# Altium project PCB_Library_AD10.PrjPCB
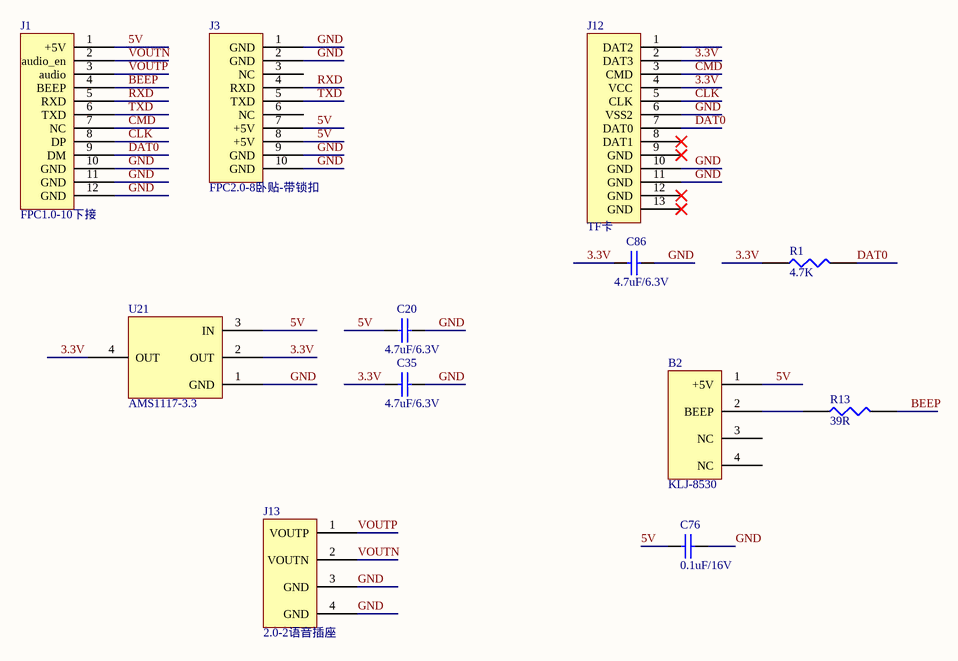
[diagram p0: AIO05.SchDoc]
6 sheets, 75 parts. Net scope: global (net labels, ports and power ports of the same name join across sheets).
Board files: AIO05.PcbDoc, AIO028-A.PcbDoc, AIO028-B.PcbDoc, AIO035-A.PcbDoc, AIO035-B.PcbDoc
Sheets:
  AIO05.SchDoc
  AIO03.SchDoc
  AIO028-A.SchDoc
  AIO028-B.SchDoc
  AIO035-A.SchDoc
  AIO035-B.SchDoc

## Sheet AIO05.SchDoc
size A4

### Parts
(Parts that share a designator on the sheet are numbered #1, #2 ... from top to bottom, then left to right.)
B2#1  KLJ-8530  [BEEP]
C20#1  4.7uF/6.3V  [0402A]
C35#1  4.7uF/6.3V  [0402A]
C76#1  0.1uF/16V  [0402A]
C86#1  4.7uF/6.3V  [0402A]
J1#1  FPC1.0-10下接  [FPC1.0-10下接]
J3#1  FPC2.0-8卧贴-带锁扣  [FPC2.0-8卧贴-带锁扣]
J12#1  TF卡  [TF卡]
J13#1  2.0-2语音插座  [2.0-2语音插座]
R1  4.7K  [0402A]
R13#1  39R  [0402A]
U21#1  AMS1117-3.3  [AMS1117-3.3]

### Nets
3.3V: C35#1.1 C86#1.1 J12#1.2(DAT3) J12#1.4(VCC) R1.1 U21#1.2(OUT) U21#1.4(OUT)
5V: B2#1.1(+5V) C20#1.1 C76#1.1 J1#1.1(+5V) J3#1.7(+5V) J3#1.8(+5V) U21#1.3(IN)
BEEP: J1#1.4(BEEP) R13#1.2
CLK: J1#1.8(DP) J12#1.5(CLK)
CMD: J1#1.7(NC) J12#1.3(CMD)
DAT0: J1#1.9(DM) J12#1.7(DAT0) R1.2
GND: C20#1.2 C35#1.2 C76#1.2 C86#1.2 J1#1.10(GND) J1#1.11(GND) J1#1.12(GND) J3#1.1(GND) J3#1.2(GND) J3#1.9(GND) J3#1.10(GND) J12#1.6(VSS2) J12#1.10(GND) J12#1.11(GND) J13#1.3(GND) J13#1.4(GND) U21#1.1(GND)
RXD: J1#1.5(RXD) J3#1.4(RXD)
TXD: J1#1.6(TXD) J3#1.5(TXD)
VOUTN: J1#1.2(audio_en) J13#1.2(VOUTN)
VOUTP: J1#1.3(audio) J13#1.1(VOUTP)
NetB2#1_2: B2#1.2(BEEP) R13#1.1

Not connected (* = marked no-connect by the designer): B2#1 3(NC) 4(NC); J3#1 3(NC) 6(NC); J12#1 1(DAT2) 8(DAT1)* 9(GND)* 12(GND)* 13(GND)*

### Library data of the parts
B2#1 = BEEP
C20#1 C35#1 C76#1 C86#1 = CAP: Capacitor
J1#1 = 1.0-10
J3#1 = 2.0-8
R1 R13#1 = RES1

## Sheet AIO03.SchDoc
size A4
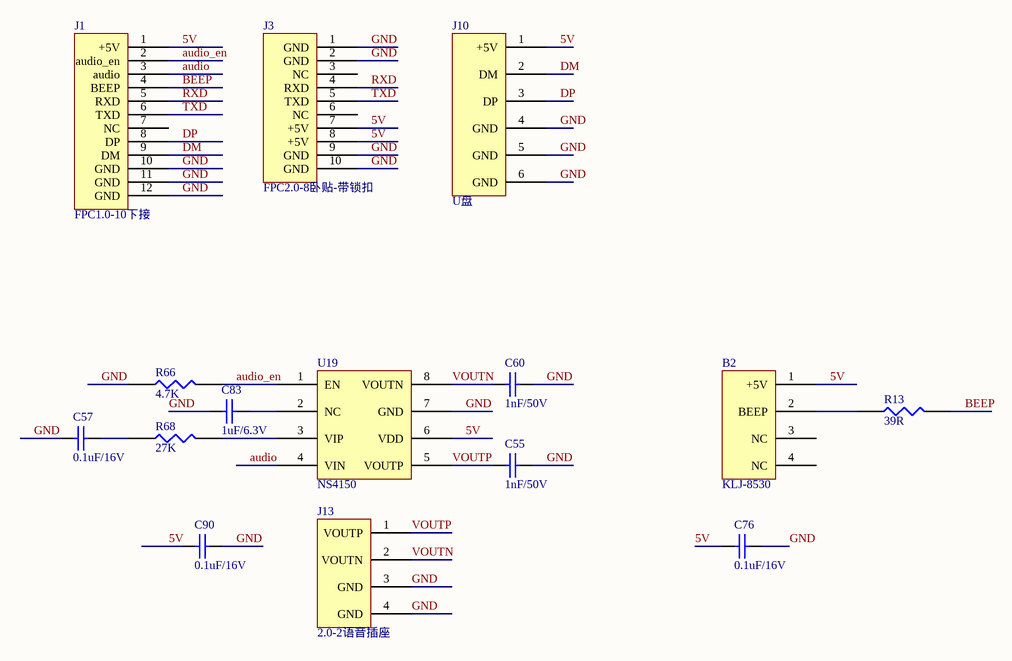
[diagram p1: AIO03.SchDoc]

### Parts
(Parts that share a designator on the sheet are numbered #1, #2 ... from top to bottom, then left to right.)
B2#2  KLJ-8530  [BEEP]
C55  1nF/50V  [0402A]
C57  0.1uF/16V  [0402A]
C60  1nF/50V  [0402A]
C76#2  0.1uF/16V  [0402A]
C83  1uF/6.3V  [0402A]
C90  0.1uF/16V  [0402A]
J1#2  FPC1.0-10下接  [FPC1.0-10下接]
J3#2  FPC2.0-8卧贴-带锁扣  [FPC2.0-8卧贴-带锁扣]
J10  U盘  [U盘]
J13#2  2.0-2语音插座  [2.0-2语音插座]
R13#2  39R  [0402A]
R66  4.7K  [0402A]
R68  27K  [0402A]
U19  NS4150  [NS4150]

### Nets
5V: B2#2.1(+5V) C76#2.1 C90.1 J1#2.1(+5V) J3#2.7(+5V) J3#2.8(+5V) J10.1(+5V) U19.6(VDD)
audio: J1#2.3(audio) U19.4(VIN)
audio_en: J1#2.2(audio_en) R66.2 U19.1(EN)
BEEP: J1#2.4(BEEP) R13#2.2
DM: J1#2.9(DM) J10.2(DM)
DP: J1#2.8(DP) J10.3(DP)
GND: C55.2 C57.1 C60.2 C76#2.2 C83.1 C90.2 J1#2.10(GND) J1#2.11(GND) J1#2.12(GND) J3#2.1(GND) J3#2.2(GND) J3#2.9(GND) J3#2.10(GND) J10.4(GND) J10.5(GND) J10.6(GND) J13#2.3(GND) J13#2.4(GND) R66.1 U19.7(GND)
RXD: J1#2.5(RXD) J3#2.4(RXD)
TXD: J1#2.6(TXD) J3#2.5(TXD)
VOUTN: C60.1 J13#2.2(VOUTN) U19.8(VOUTN)
VOUTP: C55.1 J13#2.1(VOUTP) U19.5(VOUTP)
NetB2#2_2: B2#2.2(BEEP) R13#2.1
NetC57_2: C57.2 R68.1
NetC83_2: C83.2 U19.2(NC)
NetR68_2: R68.2 U19.3(VIP)

Not connected (* = marked no-connect by the designer): B2#2 3(NC) 4(NC); J1#2 7(NC); J3#2 3(NC) 6(NC)

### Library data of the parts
B2#2 = BEEP
C55 C57 C60 C76#2 C83 C90 = CAP: Capacitor
J1#2 = 1.0-10
J3#2 = 2.0-8
R13#2 R66 R68 = RES1

## Sheet AIO028-A.SchDoc
size A4
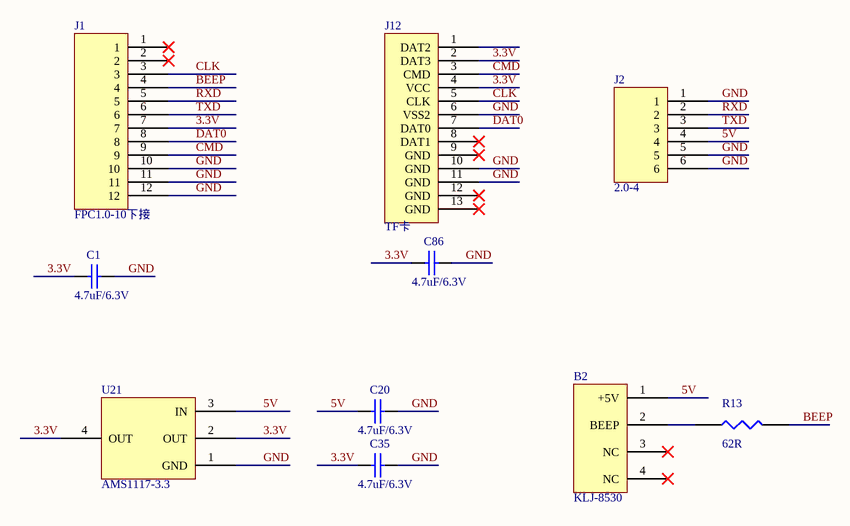
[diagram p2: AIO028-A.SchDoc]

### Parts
(Parts that share a designator on the sheet are numbered #1, #2 ... from top to bottom, then left to right.)
B2#3  KLJ-8530  [BEEP]
C1#1  4.7uF/6.3V  [0402A]
C20#2  4.7uF/6.3V  [0402A]
C35#2  4.7uF/6.3V  [0402A]
C86#2  4.7uF/6.3V  [0402A]
J1#3  FPC1.0-10下接  [FPC1.0-10下接]
J2#1  2.0-4  [FPC2.54-4]
J12#2  TF卡  [TF卡]
R13#3  62R  [0402A]
U21#2  AMS1117-3.3  [AMS1117-3.3]

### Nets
3.3V: C1#1.1 C35#2.1 C86#2.1 J1#3.7 J12#2.2(DAT3) J12#2.4(VCC) U21#2.2(OUT) U21#2.4(OUT)
5V: B2#3.1(+5V) C20#2.1 J2#1.4 U21#2.3(IN)
BEEP: J1#3.4 R13#3.2
CLK: J1#3.3 J12#2.5(CLK)
CMD: J1#3.9 J12#2.3(CMD)
DAT0: J1#3.8 J12#2.7(DAT0)
GND: C1#1.2 C20#2.2 C35#2.2 C86#2.2 J1#3.10 J1#3.11 J1#3.12 J2#1.1 J2#1.5 J2#1.6 J12#2.6(VSS2) J12#2.10(GND) J12#2.11(GND) U21#2.1(GND)
RXD: J1#3.5 J2#1.2
TXD: J1#3.6 J2#1.3
NetB2#3_2: B2#3.2(BEEP) R13#3.1

Not connected (* = marked no-connect by the designer): B2#3 3(NC)* 4(NC)*; J1#3 1* 2*; J12#2 1(DAT2) 8(DAT1)* 9(GND)* 12(GND)* 13(GND)*

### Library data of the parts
B2#3 = BEEP
C1#1 C20#2 C35#2 C86#2 = CAP: Capacitor
J1#3 = 1.0-10
R13#3 = RES1

## Sheet AIO028-B.SchDoc
size A4
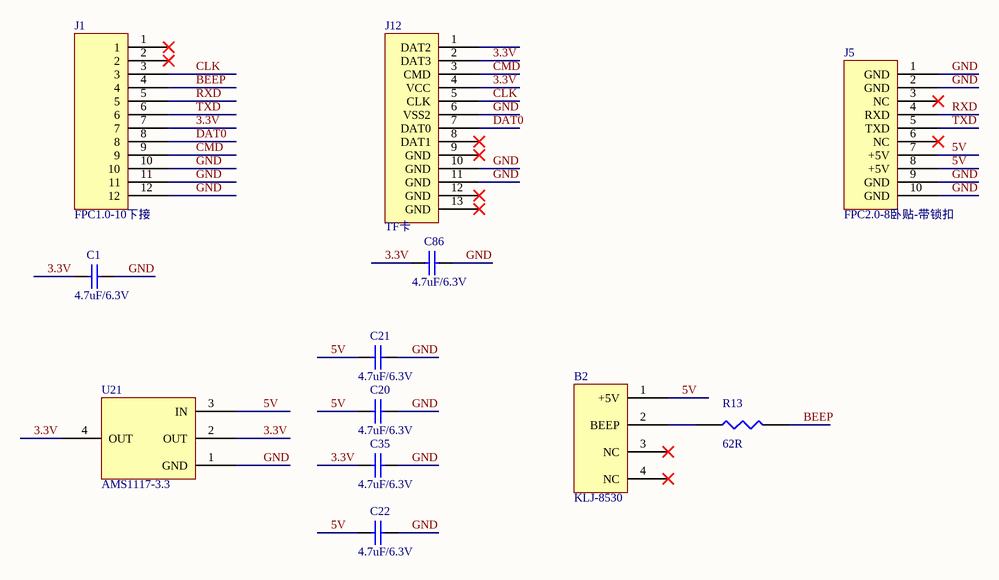
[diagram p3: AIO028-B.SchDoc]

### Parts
(Parts that share a designator on the sheet are numbered #1, #2 ... from top to bottom, then left to right.)
B2#4  KLJ-8530  [BEEP]
C1#2  4.7uF/6.3V  [0402A]
C20#3  4.7uF/6.3V  [0402A]
C21#1  4.7uF/6.3V  [0402A]
C22#1  4.7uF/6.3V  [0402A]
C35#3  4.7uF/6.3V  [0402A]
C86#3  4.7uF/6.3V  [0402A]
J1#4  FPC1.0-10下接  [FPC1.0-10下接]
J5#1  FPC2.0-8卧贴-带锁扣  [FPC2.0-8卧贴-带锁扣]
J12#3  TF卡  [TF卡]
R13#4  62R  [0402A]
U21#3  AMS1117-3.3  [AMS1117-3.3]

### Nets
3.3V: C1#2.1 C35#3.1 C86#3.1 J1#4.7 J12#3.2(DAT3) J12#3.4(VCC) U21#3.2(OUT) U21#3.4(OUT)
5V: B2#4.1(+5V) C20#3.1 C21#1.1 C22#1.1 J5#1.7(+5V) J5#1.8(+5V) U21#3.3(IN)
BEEP: J1#4.4 R13#4.2
CLK: J1#4.3 J12#3.5(CLK)
CMD: J1#4.9 J12#3.3(CMD)
DAT0: J1#4.8 J12#3.7(DAT0)
GND: C1#2.2 C20#3.2 C21#1.2 C22#1.2 C35#3.2 C86#3.2 J1#4.10 J1#4.11 J1#4.12 J5#1.1(GND) J5#1.2(GND) J5#1.9(GND) J5#1.10(GND) J12#3.6(VSS2) J12#3.10(GND) J12#3.11(GND) U21#3.1(GND)
RXD: J1#4.5 J5#1.4(RXD)
TXD: J1#4.6 J5#1.5(TXD)
NetB2#4_2: B2#4.2(BEEP) R13#4.1

Not connected (* = marked no-connect by the designer): B2#4 3(NC)* 4(NC)*; J1#4 1* 2*; J5#1 3(NC)* 6(NC)*; J12#3 1(DAT2) 8(DAT1)* 9(GND)* 12(GND)* 13(GND)*

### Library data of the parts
B2#4 = BEEP
C1#2 C20#3 C21#1 C22#1 C35#3 C86#3 = CAP: Capacitor
J1#4 = 1.0-10
J5#1 = 2.0-8
R13#4 = RES1

## Sheet AIO035-A.SchDoc
size A4
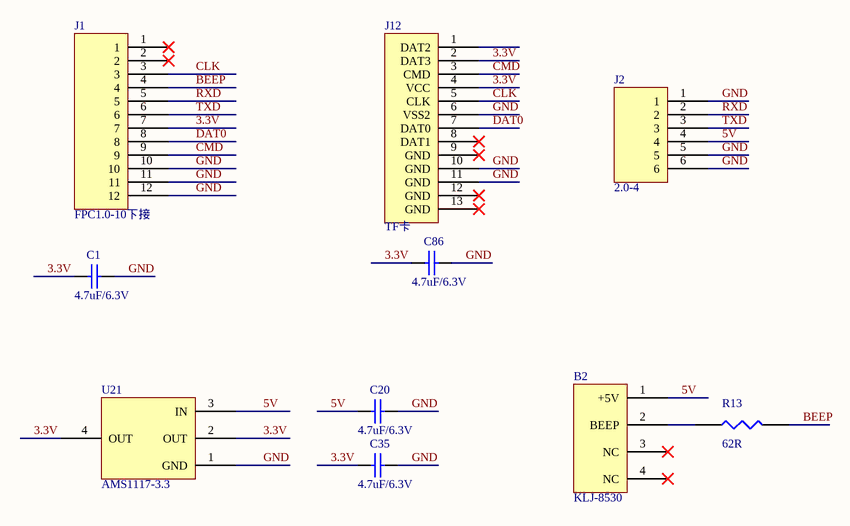
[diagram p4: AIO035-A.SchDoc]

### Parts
(Parts that share a designator on the sheet are numbered #1, #2 ... from top to bottom, then left to right.)
B2#5  KLJ-8530  [BEEP]
C1#3  4.7uF/6.3V  [0402A]
C20#4  4.7uF/6.3V  [0402A]
C35#4  4.7uF/6.3V  [0402A]
C86#4  4.7uF/6.3V  [0402A]
J1#5  FPC1.0-10下接  [FPC1.0-10下接]
J2#2  2.0-4  [FPC2.54-4]
J12#4  TF卡  [TF卡]
R13#5  62R  [0402A]
U21#4  AMS1117-3.3  [AMS1117-3.3]

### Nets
3.3V: C1#3.1 C35#4.1 C86#4.1 J1#5.7 J12#4.2(DAT3) J12#4.4(VCC) U21#4.2(OUT) U21#4.4(OUT)
5V: B2#5.1(+5V) C20#4.1 J2#2.4 U21#4.3(IN)
BEEP: J1#5.4 R13#5.2
CLK: J1#5.3 J12#4.5(CLK)
CMD: J1#5.9 J12#4.3(CMD)
DAT0: J1#5.8 J12#4.7(DAT0)
GND: C1#3.2 C20#4.2 C35#4.2 C86#4.2 J1#5.10 J1#5.11 J1#5.12 J2#2.1 J2#2.5 J2#2.6 J12#4.6(VSS2) J12#4.10(GND) J12#4.11(GND) U21#4.1(GND)
RXD: J1#5.5 J2#2.2
TXD: J1#5.6 J2#2.3
NetB2#5_2: B2#5.2(BEEP) R13#5.1

Not connected (* = marked no-connect by the designer): B2#5 3(NC)* 4(NC)*; J1#5 1* 2*; J12#4 1(DAT2) 8(DAT1)* 9(GND)* 12(GND)* 13(GND)*

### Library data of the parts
B2#5 = BEEP
C1#3 C20#4 C35#4 C86#4 = CAP: Capacitor
J1#5 = 1.0-10
R13#5 = RES1

## Sheet AIO035-B.SchDoc
size A4
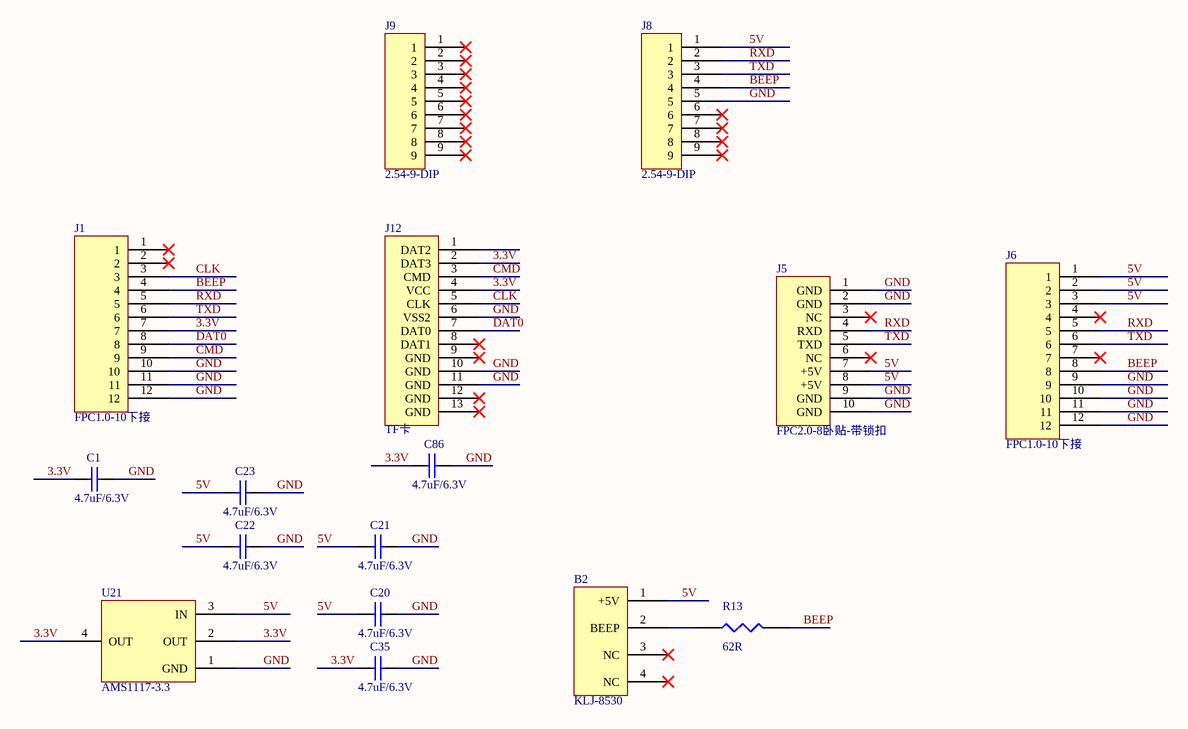
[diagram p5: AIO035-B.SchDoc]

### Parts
(Parts that share a designator on the sheet are numbered #1, #2 ... from top to bottom, then left to right.)
B2#6  KLJ-8530  [BEEP]
C1#4  4.7uF/6.3V  [0402A]
C20#5  4.7uF/6.3V  [0402A]
C21#2  4.7uF/6.3V  [0402A]
C22#2  4.7uF/6.3V  [0402A]
C23  4.7uF/6.3V  [0402A]
C35#5  4.7uF/6.3V  [0402A]
C86#5  4.7uF/6.3V  [0402A]
J1#6  FPC1.0-10下接  [FPC1.0-10下接]
J5#2  FPC2.0-8卧贴-带锁扣  [FPC2.0-8卧贴-带锁扣]
J6  FPC1.0-10下接  [FPC1.0-10下接]
J8  2.54-9-DIP  [2.54-9-DIP]
J9  2.54-9-DIP
J12#5  TF卡  [TF卡]
R13#6  62R  [0402A]
U21#5  AMS1117-3.3  [AMS1117-3.3]

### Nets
3.3V: C1#4.1 C35#5.1 C86#5.1 J1#6.7 J12#5.2(DAT3) J12#5.4(VCC) U21#5.2(OUT) U21#5.4(OUT)
5V: B2#6.1(+5V) C20#5.1 C21#2.1 C22#2.1 C23.1 J5#2.7(+5V) J5#2.8(+5V) J6.1 J6.2 J6.3 J8.1 U21#5.3(IN)
BEEP: J1#6.4 J6.8 J8.4 R13#6.2
CLK: J1#6.3 J12#5.5(CLK)
CMD: J1#6.9 J12#5.3(CMD)
DAT0: J1#6.8 J12#5.7(DAT0)
GND: C1#4.2 C20#5.2 C21#2.2 C22#2.2 C23.2 C35#5.2 C86#5.2 J1#6.10 J1#6.11 J1#6.12 J5#2.1(GND) J5#2.2(GND) J5#2.9(GND) J5#2.10(GND) J6.9 J6.10 J6.11 J6.12 J8.5 J12#5.6(VSS2) J12#5.10(GND) J12#5.11(GND) U21#5.1(GND)
RXD: J1#6.5 J5#2.4(RXD) J6.5 J8.2
TXD: J1#6.6 J5#2.5(TXD) J6.6 J8.3
NetB2#6_2: B2#6.2(BEEP) R13#6.1

Not connected (* = marked no-connect by the designer): B2#6 3(NC)* 4(NC)*; J1#6 1* 2*; J5#2 3(NC)* 6(NC)*; J6 4* 7*; J8 6* 7* 8* 9*; J9 1* 2* 3* 4* 5* 6* 7* 8* 9*; J12#5 1(DAT2) 8(DAT1)* 9(GND)* 12(GND)* 13(GND)*

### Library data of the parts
B2#6 = BEEP
C1#4 C20#5 C21#2 C22#2 C23 C35#5 C86#5 = CAP: Capacitor
J1#6 J6 = 1.0-10
J5#2 = 2.0-8
R13#6 = RES1

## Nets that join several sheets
3.3V: AIO05 (7 pins), AIO028-A (8 pins), AIO028-B (8 pins), AIO035-A (8 pins), AIO035-B (8 pins)
5V: AIO05 (7 pins), AIO03 (8 pins), AIO028-A (B2#3.1 C20#2.1 J2#1.4 U21#2.3), AIO028-B (7 pins), AIO035-A (B2#5.1 C20#4.1 J2#2.4 U21#4.3), AIO035-B (12 pins)
BEEP: AIO05 (J1#1.4 R13#1.2), AIO03 (J1#2.4 R13#2.2), AIO028-A (J1#3.4 R13#3.2), AIO028-B (J1#4.4 R13#4.2), AIO035-A (J1#5.4 R13#5.2), AIO035-B (J1#6.4 J6.8 J8.4 R13#6.2)
CLK: AIO05 (J1#1.8 J12#1.5), AIO028-A (J1#3.3 J12#2.5), AIO028-B (J1#4.3 J12#3.5), AIO035-A (J1#5.3 J12#4.5), AIO035-B (J1#6.3 J12#5.5)
CMD: AIO05 (J1#1.7 J12#1.3), AIO028-A (J1#3.9 J12#2.3), AIO028-B (J1#4.9 J12#3.3), AIO035-A (J1#5.9 J12#4.3), AIO035-B (J1#6.9 J12#5.3)
DAT0: AIO05 (J1#1.9 J12#1.7 R1.2), AIO028-A (J1#3.8 J12#2.7), AIO028-B (J1#4.8 J12#3.7), AIO035-A (J1#5.8 J12#4.7), AIO035-B (J1#6.8 J12#5.7)
GND: AIO05 (17 pins), AIO03 (20 pins), AIO028-A (14 pins), AIO028-B (17 pins), AIO035-A (14 pins), AIO035-B (23 pins)
RXD: AIO05 (J1#1.5 J3#1.4), AIO03 (J1#2.5 J3#2.4), AIO028-A (J1#3.5 J2#1.2), AIO028-B (J1#4.5 J5#1.4), AIO035-A (J1#5.5 J2#2.2), AIO035-B (J1#6.5 J5#2.4 J6.5 J8.2)
TXD: AIO05 (J1#1.6 J3#1.5), AIO03 (J1#2.6 J3#2.5), AIO028-A (J1#3.6 J2#1.3), AIO028-B (J1#4.6 J5#1.5), AIO035-A (J1#5.6 J2#2.3), AIO035-B (J1#6.6 J5#2.5 J6.6 J8.3)
VOUTN: AIO05 (J1#1.2 J13#1.2), AIO03 (C60.1 J13#2.2 U19.8)
VOUTP: AIO05 (J1#1.3 J13#1.1), AIO03 (C55.1 J13#2.1 U19.5)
